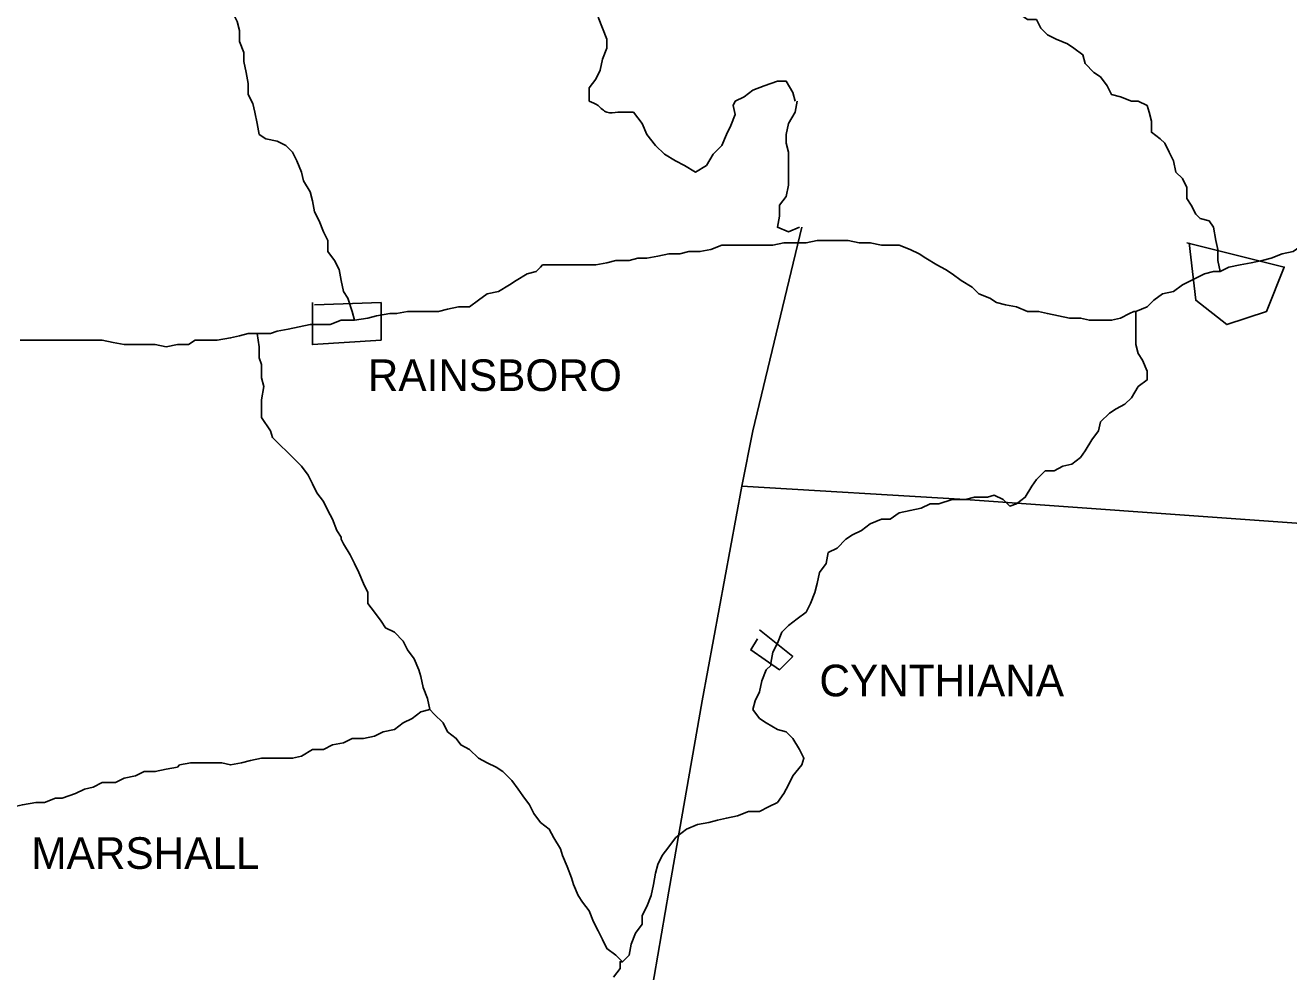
# Model space of a CAD drawing. Extents: x 0 to 40.2, y 0 to 22.
# Drawn here: x 4.34 to 5.119, y 18.212 to 18.795 of the extents above; entities that cross this region are included whole.
import ezdxf

# ---------------------------------------------------------------- set-up
doc = ezdxf.new("R2010")
doc.units = 0
doc.layers.add('Default', color=7, linetype='Continuous')

msp = doc.modelspace()

# ---------------------------------------------------------------- linework, layer by layer
at = {"layer": 'Default'}
for points in [[(5.02585, 18.74817), (5.02176, 18.74817), (5.01495, 18.7509), (5.00949, 18.75226), (5.00677, 18.75772), (5.00268, 18.76317), (4.99859, 18.7659), (4.99313, 18.77135), (4.99177, 18.7768), (4.98632, 18.78089), (4.98223, 18.78362), (4.97541, 18.78635), (4.96995, 18.78907), (4.96586, 18.79316), (4.96314, 18.79862), (4.95768, 18.79862), (4.95359, 18.80135), (4.95087, 18.8068), (4.94814, 18.81362), (4.94678, 18.81498), (4.94678, 18.81498)], [(4.48458, 18.72772), (4.48321, 18.73454), (4.48185, 18.74135), (4.48049, 18.74681), (4.47776, 18.75226), (4.47776, 18.75908), (4.4764, 18.7659), (4.47503, 18.77271), (4.47503, 18.77817), (4.47231, 18.78498), (4.47231, 18.7918), (4.47094, 18.79725), (4.46822, 18.80271), (4.46276, 18.8068)], [(4.68773, 18.74817), (4.68773, 18.75635), (4.69182, 18.76181), (4.69454, 18.76726), (4.69591, 18.77408), (4.69863, 18.78089), (4.69863, 18.78635), (4.69591, 18.79316), (4.69318, 18.79998)], [(4.81452, 18.74817), (4.81316, 18.75363), (4.80907, 18.76044), (4.80362, 18.76044), (4.79544, 18.75772), (4.78862, 18.75499), (4.78317, 18.7509), (4.77771, 18.74817)], [(4.70954, 18.74135), (4.71499, 18.74135), (4.72045, 18.73454), (4.72318, 18.72772), (4.72863, 18.7209), (4.73408, 18.71545), (4.7409, 18.71136), (4.74635, 18.70863), (4.75317, 18.70454), (4.75999, 18.70863), (4.76408, 18.71545), (4.76953, 18.7209), (4.77226, 18.72772), (4.77499, 18.73317), (4.77771, 18.73999), (4.77635, 18.74545), (4.77771, 18.74817)], [(4.81589, 18.74817), (4.81452, 18.74135), (4.81043, 18.73454), (4.80907, 18.72772), (4.80907, 18.72227), (4.81043, 18.71681), (4.81043, 18.71), (4.81043, 18.70318), (4.81043, 18.69636), (4.80907, 18.68954), (4.80498, 18.68409), (4.80498, 18.67727), (4.80362, 18.67046), (4.81043, 18.66773), (4.81725, 18.67046)], [(5.0763, 18.64319), (5.07494, 18.65001), (5.07494, 18.65682), (5.07357, 18.66228), (5.07221, 18.67046), (5.06948, 18.67455), (5.06403, 18.67591), (5.0613, 18.67864), (5.05858, 18.68409), (5.05585, 18.68818), (5.05585, 18.695), (5.05312, 18.70045), (5.04903, 18.70454), (5.04767, 18.71136), (5.04494, 18.71681), (5.04222, 18.72227), (5.03949, 18.72499), (5.03404, 18.72908), (5.03404, 18.7359), (5.03267, 18.74135), (5.03131, 18.74545), (5.02585, 18.74817), (5.02585, 18.74817)], [(4.5432, 18.61319), (4.54184, 18.61865), (4.53911, 18.62683), (4.53639, 18.63092), (4.53502, 18.63773), (4.53366, 18.64455), (4.53093, 18.65001), (4.52684, 18.65546), (4.52684, 18.66228), (4.52412, 18.66773), (4.52139, 18.67455), (4.51866, 18.68), (4.5173, 18.68682), (4.51594, 18.69227), (4.51185, 18.69909), (4.51048, 18.70454), (4.50775, 18.71136), (4.50503, 18.71681), (4.50094, 18.7209), (4.49548, 18.72363), (4.48867, 18.72499), (4.48458, 18.72772), (4.48458, 18.72772)], [(4.7818, 18.51094), (4.78862, 18.54502), (4.81861, 18.67046)], [(5.0763, 18.64319), (5.08176, 18.64592), (5.08857, 18.64728), (5.09539, 18.64864), (5.10221, 18.65001), (5.10766, 18.65137), (5.11448, 18.6541), (5.12129, 18.65546), (5.12675, 18.65955), (5.1322, 18.66091), (5.13902, 18.66228), (5.14447, 18.66637), (5.14993, 18.66773), (5.15674, 18.67046), (5.1622, 18.67318), (5.16629, 18.67455), (5.16629, 18.67455)], [(4.65909, 18.64728), (4.66591, 18.64728), (4.67273, 18.64728), (4.67955, 18.64728), (4.68636, 18.64728), (4.69182, 18.64728), (4.69863, 18.64864), (4.70409, 18.65001), (4.71227, 18.65001), (4.71772, 18.65137), (4.72318, 18.65137), (4.72999, 18.65273), (4.73681, 18.6541), (4.74363, 18.6541), (4.74908, 18.65546), (4.7559, 18.65546), (4.76271, 18.65682), (4.76953, 18.65955), (4.77499, 18.65955), (4.78044, 18.65955), (4.78726, 18.65955), (4.79407, 18.65955), (4.80089, 18.65955), (4.80771, 18.66091), (4.81316, 18.66091), (4.81589, 18.66091)], [(4.81589, 18.66091), (4.82134, 18.66091), (4.82816, 18.66228), (4.83498, 18.66228), (4.84043, 18.66228), (4.84725, 18.66228), (4.85406, 18.66091), (4.86088, 18.66091), (4.8677, 18.65955), (4.87315, 18.65955), (4.87861, 18.65955), (4.88542, 18.65682), (4.89088, 18.6541), (4.89497, 18.65137), (4.90178, 18.64728), (4.90724, 18.64455), (4.91133, 18.64183), (4.91678, 18.63773), (4.9236, 18.63364), (4.92769, 18.62955), (4.93451, 18.62683), (4.9386, 18.6241), (4.94405, 18.62274), (4.95087, 18.62137), (4.95768, 18.61865), (4.9645, 18.61865), (4.96995, 18.61728), (4.97677, 18.61592), (4.98359, 18.61456), (4.99041, 18.61456), (4.99586, 18.61319), (5.00131, 18.61319), (5.00949, 18.61319), (5.01495, 18.61456), (5.0204, 18.61728), (5.02313, 18.61865), (5.02449, 18.61865)], [(5.05721, 18.66091), (5.0613, 18.62546), (5.08039, 18.61047), (5.10493, 18.61865), (5.11584, 18.64592), (5.05585, 18.66091)], [(4.5432, 18.61319), (4.55138, 18.61456), (4.55684, 18.61592), (4.56502, 18.61728), (4.56911, 18.61728), (4.57593, 18.61865), (4.58274, 18.61865), (4.58956, 18.61865), (4.59501, 18.61865), (4.60047, 18.62001), (4.60728, 18.62137), (4.6141, 18.62137), (4.61956, 18.62546), (4.62501, 18.62955), (4.63183, 18.63092), (4.63864, 18.63501), (4.64273, 18.63773), (4.64955, 18.64183), (4.655, 18.64319), (4.65773, 18.64592), (4.65909, 18.64728)], [(5.02449, 18.61865), (5.03131, 18.62137), (5.0354, 18.62546), (5.04085, 18.62955), (5.04767, 18.63092), (5.05312, 18.63501), (5.05858, 18.63773), (5.05858, 18.63773)], [(5.02449, 18.61865), (5.03131, 18.62137), (5.0354, 18.62546), (5.04085, 18.62955), (5.04767, 18.63092), (5.05312, 18.63501), (5.05858, 18.63773), (5.05858, 18.63773)], [(5.05858, 18.63773), (5.06676, 18.64183), (5.07221, 18.64319), (5.0763, 18.64319)], [(5.05858, 18.63773), (5.06676, 18.64183), (5.07221, 18.64319), (5.0763, 18.64319)], [(4.51866, 18.62274), (4.55956, 18.6241), (4.55956, 18.60092), (4.5173, 18.5982), (4.5173, 18.6241)], [(4.48321, 18.60501), (4.49139, 18.60501), (4.49548, 18.60638), (4.5023, 18.60774), (4.50912, 18.6091), (4.51594, 18.61047), (4.52139, 18.61047), (4.52821, 18.61047), (4.53502, 18.61319), (4.54184, 18.61319), (4.5432, 18.61319)], [(4.48321, 18.60501), (4.49139, 18.60501), (4.49548, 18.60638), (4.5023, 18.60774), (4.50912, 18.6091), (4.51594, 18.61047), (4.52139, 18.61047), (4.52821, 18.61047), (4.53502, 18.61319), (4.54184, 18.61319), (4.5432, 18.61319)], [(4.91951, 18.50276), (4.92496, 18.50412), (4.93314, 18.50412), (4.93723, 18.50548), (4.94269, 18.50276), (4.94678, 18.49867), (4.95087, 18.50003), (4.95632, 18.50412), (4.96041, 18.51094), (4.96314, 18.51503), (4.96859, 18.52048), (4.97404, 18.52048), (4.9795, 18.52321), (4.98495, 18.52457), (4.99041, 18.52866), (4.99313, 18.53275), (4.99722, 18.53957), (5.00131, 18.54502), (5.00268, 18.55048), (5.00813, 18.55593), (5.01222, 18.55866), (5.01767, 18.56138), (5.02176, 18.56547), (5.02585, 18.57229), (5.03131, 18.57638), (5.03131, 18.58183), (5.02858, 18.58865), (5.02585, 18.59274), (5.02449, 18.5982), (5.02449, 18.60501), (5.02449, 18.61047), (5.02449, 18.61865), (5.02449, 18.61865), (5.02449, 18.61865)], [(4.33733, 18.60092), (4.34414, 18.60092), (4.3496, 18.60092), (4.35642, 18.60092), (4.36323, 18.60092), (4.36869, 18.60092), (4.37687, 18.60092), (4.38232, 18.60092), (4.38777, 18.60092), (4.39459, 18.59956), (4.40141, 18.5982), (4.40823, 18.5982), (4.41368, 18.5982), (4.4205, 18.5982), (4.42731, 18.59683), (4.43413, 18.5982), (4.44095, 18.5982), (4.44504, 18.60092), (4.45322, 18.60092), (4.45867, 18.60092), (4.46685, 18.60229), (4.47231, 18.60365), (4.47776, 18.60501), (4.48321, 18.60501)], [(4.53502, 18.47958), (4.5323, 18.48367), (4.52957, 18.49049), (4.52684, 18.49594), (4.52412, 18.50139), (4.52003, 18.50685), (4.5173, 18.5123), (4.51457, 18.51775), (4.51048, 18.52321), (4.50639, 18.5273), (4.5023, 18.53139), (4.49685, 18.53684), (4.49276, 18.54093), (4.49139, 18.54502), (4.48594, 18.5532), (4.48594, 18.55866), (4.48594, 18.56411), (4.4873, 18.57229), (4.48594, 18.57774), (4.48594, 18.58592), (4.48458, 18.59002), (4.48458, 18.59683), (4.48321, 18.60501), (4.48321, 18.60501)], [(4.7818, 18.51094), (4.75726, 18.37868), (4.73681, 18.26143), (4.72318, 18.18235), (4.70818, 18.10191), (4.69182, 18.01601), (4.66182, 17.86877)], [(4.7818, 18.51094), (4.91951, 18.50276), (5.49078, 18.46185), (6.12205, 18.41686), (6.78194, 18.36778)], [(4.79953, 18.40186), (4.80089, 18.40868), (4.80362, 18.41413), (4.80634, 18.42095), (4.81043, 18.42504), (4.81589, 18.42913), (4.82134, 18.43322), (4.82407, 18.43868), (4.8268, 18.44549), (4.82816, 18.45095), (4.82952, 18.45776), (4.83361, 18.46322), (4.83498, 18.47003), (4.84043, 18.47276), (4.84588, 18.47821), (4.84997, 18.48094), (4.85543, 18.48367), (4.86088, 18.48776), (4.8677, 18.49049), (4.87315, 18.49049), (4.87861, 18.49458), (4.88542, 18.49594), (4.89224, 18.4973), (4.89769, 18.50003), (4.90315, 18.50003), (4.91133, 18.50276), (4.91678, 18.50276), (4.91951, 18.50276)], [(4.58956, 18.37323), (4.5882, 18.38005), (4.58547, 18.38687), (4.58411, 18.39368), (4.58274, 18.39777), (4.58002, 18.40459), (4.57593, 18.41004), (4.5732, 18.4155), (4.56775, 18.42095), (4.56229, 18.42368), (4.55956, 18.42777), (4.55547, 18.43322), (4.55138, 18.43868), (4.55138, 18.44549), (4.54866, 18.45095), (4.54593, 18.45776), (4.5432, 18.46322), (4.54048, 18.46867), (4.53639, 18.47549), (4.53502, 18.47821), (4.53502, 18.47958)], [(4.79135, 18.41686), (4.78726, 18.41004), (4.80498, 18.39777), (4.81316, 18.40595), (4.79271, 18.42231)], [(4.74226, 18.29552), (4.74772, 18.29961), (4.75453, 18.30233), (4.76135, 18.3037), (4.7668, 18.30506), (4.77226, 18.30642), (4.77908, 18.30779), (4.78589, 18.31051), (4.79271, 18.31051), (4.79816, 18.31324), (4.80362, 18.31597), (4.80771, 18.32142), (4.81043, 18.32687), (4.81316, 18.33233), (4.81861, 18.33915), (4.81998, 18.34324), (4.81725, 18.34869), (4.81316, 18.35551), (4.80907, 18.3596), (4.80362, 18.36096), (4.7968, 18.36505), (4.79271, 18.36778), (4.78862, 18.37323), (4.78998, 18.37868), (4.79271, 18.38414), (4.79407, 18.39096), (4.7968, 18.39777), (4.79953, 18.4005), (4.79953, 18.40186)], [(4.43549, 18.33915), (4.44231, 18.34051), (4.44776, 18.34051), (4.45322, 18.34051), (4.4614, 18.34051), (4.46685, 18.33915), (4.47367, 18.34051), (4.47912, 18.34187), (4.48594, 18.34324), (4.49276, 18.34324), (4.49957, 18.34324), (4.50503, 18.34324), (4.51048, 18.3446), (4.5173, 18.34869), (4.52412, 18.34869), (4.52957, 18.35142), (4.53639, 18.35278), (4.54184, 18.35551), (4.54866, 18.35551), (4.55547, 18.35687), (4.56093, 18.3596), (4.56775, 18.36096), (4.5732, 18.36505), (4.57865, 18.36778), (4.58411, 18.37187), (4.58956, 18.37323)], [(4.70818, 18.2178), (4.70409, 18.22189), (4.69863, 18.22598), (4.69591, 18.23144), (4.69318, 18.23689), (4.69045, 18.24234), (4.68773, 18.24916), (4.68364, 18.25461), (4.68091, 18.2587), (4.67818, 18.26552), (4.67682, 18.26961), (4.67409, 18.27643), (4.67137, 18.28325), (4.67, 18.28734), (4.66591, 18.29415), (4.66318, 18.29961), (4.65773, 18.3037), (4.65364, 18.30915), (4.65091, 18.3146), (4.64682, 18.32006), (4.6441, 18.32415), (4.64001, 18.3296), (4.63455, 18.33506), (4.63046, 18.33778), (4.62501, 18.34051), (4.61956, 18.34324), (4.6141, 18.34869), (4.60865, 18.35142), (4.60592, 18.35551), (4.60047, 18.3596), (4.59774, 18.36505), (4.59229, 18.3705), (4.58956, 18.37323), (4.58956, 18.37323), (4.58956, 18.37323)], [(4.31551, 18.30915), (4.32233, 18.30915), (4.32778, 18.31051), (4.33324, 18.31324), (4.33869, 18.3146), (4.34687, 18.31597), (4.35233, 18.31597), (4.35914, 18.31869), (4.36323, 18.31869), (4.37141, 18.32142), (4.37687, 18.32415), (4.38232, 18.32551), (4.38777, 18.32824), (4.39595, 18.32824), (4.40141, 18.33097), (4.40823, 18.33233), (4.41368, 18.33506), (4.4205, 18.33506), (4.42731, 18.33642), (4.43413, 18.33778), (4.43549, 18.33915)], [(4.70818, 18.2178), (4.71227, 18.22189), (4.71363, 18.22871), (4.71636, 18.23553), (4.72045, 18.24098), (4.72045, 18.24643), (4.72318, 18.25189), (4.7259, 18.2587), (4.72727, 18.26552), (4.72863, 18.27234), (4.72999, 18.27779), (4.73272, 18.28325), (4.73681, 18.2887), (4.7409, 18.29415), (4.74226, 18.29552)], [(4.70272, 18.20826), (4.70681, 18.21371), (4.70681, 18.2178), (4.70681, 18.2178), (4.70818, 18.2178)]]:
    msp.add_lwpolyline(points, dxfattribs=at)
msp.add_spline([(4.68773, 18.74817), (4.69318, 18.74545), (4.69863, 18.74135), (4.70545, 18.74135), (4.70954, 18.74135)], degree=3, dxfattribs=at)

# ---------------------------------------------------------------- texts
for s, p in [('RAINSBORO', (4.55138, 18.56956)), ('CYNTHIANA', (4.82952, 18.38141)), ('MARSHALL', (4.34414, 18.27506))]:
    msp.add_text(s, height=0.019502, dxfattribs=at).set_placement(p)

doc.saveas('drawing.dxf')
